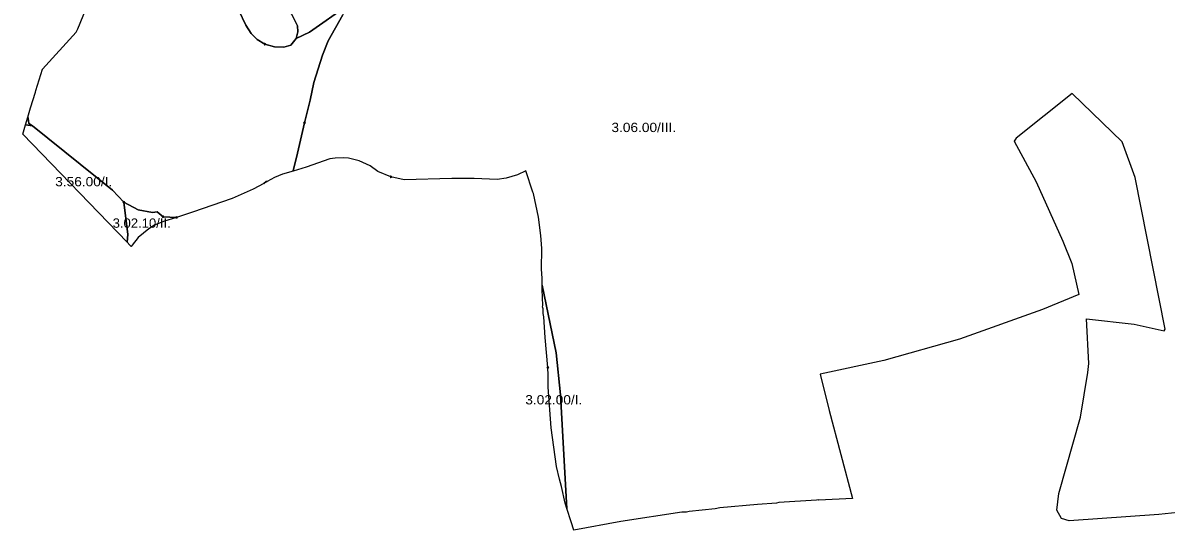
# Model space of a CAD drawing. Extents: x -650455 to -642254, y -1075222 to -1066610.
# Drawn here: x -645645 to -644416, y -1073659 to -1073114 of the extents above; entities that cross this region are included whole.
import ezdxf
from ezdxf.enums import TextEntityAlignment as Align

# ---------------------------------------------------------------- set-up
doc = ezdxf.new("R2010")
doc.units = 0
doc.header["$LTSCALE"] = 4
doc.header["$PDMODE"] = 32
doc.header["$PDSIZE"] = 2
for name, color, linetype, lineweight in [('1', 7, 'Continuous', 25), ('11', 7, 'Continuous', 13), ('12', 7, 'Continuous', 13), ('13', 7, 'Continuous', 13), ('14', 7, 'Continuous', 13)]:
    doc.layers.add(name, color=color, linetype=linetype, lineweight=lineweight)
doc.layers.add('2', color=7, linetype='Continuous')

msp = doc.modelspace()

# ---------------------------------------------------------------- linework, layer by layer
at = {"layer": '1'}
for points in [[(-645351.243, -1073131.207), (-645357.013, -1073138.376), (-645364.358, -1073140.474), (-645374.499, -1073140.125), (-645384.641, -1073137.152), (-645393.034, -1073132.256), (-645399.679, -1073125.611), (-645405.274, -1073116.694), (-645412.618, -1073101.131), (-645418.563, -1073077.351), (-645423.109, -1073054.795), (-645415.59, -1073061.089), (-645393.558, -1073075.428), (-645375.373, -1073085.744), (-645364.532, -1073094.137), (-645360.161, -1073098.159), (-645354.74, -1073107.426), (-645349.844, -1073117.568), (-645349.32, -1073124.038)], [(-645638.532, -1073222.307), (-645634.5, -1073225.001), (-645641.977, -1073223.681), (-645639.672, -1073215.65), (-645639.079, -1073216.724)], [(-645532, -1073341.501), (-645532.942, -1073349.981), (-645644.929, -1073233.97), (-645641.977, -1073223.681), (-645634.5, -1073225.001), (-645548.5, -1073294.001), (-645536.5, -1073307)], [(-645382.453, -1073284.826), (-645386.001, -1073286.755), (-645383.329, -1073284.731)], [(-645521, -1073315), (-645505.5, -1073318.001), (-645500.597, -1073317.109), (-645494.276, -1073322.5), (-645479.792, -1073323.208), (-645493.898, -1073327.697), (-645503.277, -1073331.676), (-645509.529, -1073335.37), (-645520.898, -1073344.89), (-645527.577, -1073353.132), (-645528.504, -1073354.578), (-645530.085, -1073352.941), (-645532.942, -1073349.981), (-645532, -1073341.501), (-645536.5, -1073307)], [(-645060.1, -1073635.952), (-645061.878, -1073630.295), (-645065.97, -1073612.516), (-645068.228, -1073604.614), (-645071.191, -1073590.784), (-645076.977, -1073549.296), (-645080.222, -1073505.551), (-645080.081, -1073492.851), (-645080.505, -1073484.384), (-645083.609, -1073452.21), (-645085.02, -1073430.198), (-645085.585, -1073426.529), (-645085.585, -1073421.449), (-645086.149, -1073419.472), (-645085.867, -1073417.78), (-645086.714, -1073400.563), (-645086.714, -1073396.177), (-645071.473, -1073468.855), (-645066.839, -1073513.793)]]:
    msp.add_lwpolyline(points, close=True, dxfattribs=at)
for points in [[(-645322.654, -1073149.042), (-645332.097, -1073178.418), (-645335.943, -1073197.478), (-645342.151, -1073221.608), (-645349.757, -1073254.306), (-645354.478, -1073273.19), (-645354.488, -1073273.432), (-645366.002, -1073276.823), (-645374.529, -1073280.517), (-645382.453, -1073284.826), (-645383.329, -1073284.731), (-645386.001, -1073286.755), (-645397.266, -1073292.881), (-645420.003, -1073302.828), (-645462.634, -1073317.748), (-645479.792, -1073323.208), (-645494.276, -1073322.5), (-645500.597, -1073317.109), (-645505.5, -1073318.001), (-645521, -1073315), (-645536.5, -1073307), (-645548.5, -1073294.001), (-645634.5, -1073225.001), (-645638.532, -1073222.307), (-645639.079, -1073216.724), (-645639.672, -1073215.65), (-645636.773, -1073205.545), (-645631.269, -1073188.612), (-645631.128, -1073186.919), (-645623.649, -1073164.198), (-645587.806, -1073124.405), (-645585.831, -1073120.596), (-645576.8, -1073098.864)], [(-645412.618, -1073101.131), (-645405.274, -1073116.694), (-645399.679, -1073125.611), (-645393.034, -1073132.256), (-645384.641, -1073137.152), (-645374.499, -1073140.125), (-645364.358, -1073140.474), (-645357.013, -1073138.376), (-645351.243, -1073131.207), (-645336.905, -1073124.213), (-645294.852, -1073094.837)], [(-645294.852, -1073094.837), (-645336.905, -1073124.213), (-645351.243, -1073131.207), (-645349.32, -1073124.038), (-645349.844, -1073117.568), (-645354.74, -1073107.426)], [(-645086.714, -1073396.177), (-645086.714, -1073388.427), (-645087.278, -1073378.832), (-645086.996, -1073356.537), (-645088.125, -1073342.708), (-645090.524, -1073322.952), (-645096.027, -1073297.551), (-645096.874, -1073295.999), (-645104.297, -1073273.411), (-645113.053, -1073277.391), (-645125.558, -1073281.086), (-645134.938, -1073282.648), (-645159.948, -1073281.511), (-645183.822, -1073281.511), (-645234.98, -1073282.791), (-645249.191, -1073279.665), (-645263.402, -1073273.98), (-645271.501, -1073267.869), (-645283.581, -1073262.328), (-645294.949, -1073259.77), (-645300.633, -1073259.2), (-645309.16, -1073259.627), (-645314.844, -1073260.48), (-645340.423, -1073269.29), (-645354.488, -1073273.432), (-645354.478, -1073273.19), (-645349.757, -1073254.306), (-645342.151, -1073221.608), (-645335.943, -1073197.478), (-645332.097, -1073178.418), (-645322.654, -1073149.042), (-645316.797, -1073133.48), (-645301.06, -1073105.503)], [(-645301.06, -1073105.503), (-645316.797, -1073133.48), (-645322.654, -1073149.042)], [(-644508.15, -1073538.007), (-644499.965, -1073489.748), (-644499.118, -1073480.04), (-644501.498, -1073432.196), (-644450.153, -1073438.099), (-644418.12, -1073445.155), (-644416.85, -1073443.462), (-644449.165, -1073280.335), (-644463.276, -1073242.235), (-644516.891, -1073190.139), (-644577.295, -1073238.143), (-644579.271, -1073241.528), (-644555.705, -1073285.133), (-644526.918, -1073348.634), (-644517.463, -1073372.622), (-644509.633, -1073406.043), (-644549.004, -1073422.171), (-644638.115, -1073454.186), (-644719.397, -1073476.905), (-644787.865, -1073491.654), (-644778.163, -1073530.809), (-644753.225, -1073625.103), (-644789.247, -1073627.05), (-644789.812, -1073626.485), (-644791.646, -1073627.05), (-644832.287, -1073629.59), (-644834.827, -1073630.155), (-644855.147, -1073631.566), (-644895.788, -1073635.376), (-644900.868, -1073636.223), (-644928.808, -1073639.185), (-644931.348, -1073639.89), (-644936.429, -1073640.033), (-645002.046, -1073649.911), (-645052.793, -1073659.198), (-645055.646, -1073650.122), (-645060.1, -1073635.952), (-645066.839, -1073513.793), (-645071.473, -1073468.855), (-645086.714, -1073396.177)], [(-644376.209, -1073637.35), (-644423.623, -1073642.431), (-644520.145, -1073649.204), (-644528.329, -1073646.806), (-644533.268, -1073637.633), (-644531.151, -1073619.854), (-644508.15, -1073538.007)]]:
    msp.add_lwpolyline(points, dxfattribs=at)
at = {"layer": '11'}
for points in [[(-645536.5, -1073307), (-645548.5, -1073294.001), (-645634.5, -1073225.001), (-645641.977, -1073223.681), (-645644.929, -1073233.97), (-645532.942, -1073349.981)], [(-645532.942, -1073349.981), (-645532, -1073341.501), (-645536.5, -1073307)]]:
    msp.add_lwpolyline(points, dxfattribs=at)
msp.add_lwpolyline([(-645080.505, -1073484.384), (-645080.081, -1073492.851), (-645080.222, -1073505.551), (-645076.977, -1073549.296), (-645071.191, -1073590.784), (-645068.228, -1073604.614), (-645065.97, -1073612.516), (-645061.878, -1073630.295), (-645060.1, -1073635.952), (-645066.839, -1073513.793), (-645071.473, -1073468.855), (-645086.714, -1073396.177), (-645086.714, -1073400.563), (-645085.867, -1073417.78), (-645086.149, -1073419.472), (-645085.585, -1073421.449), (-645085.585, -1073426.529), (-645085.02, -1073430.198), (-645083.609, -1073452.21)], close=True, dxfattribs=at)
for p in [(-645536.5, -1073307), (-645080.505, -1073484.384)]:
    msp.add_point(p, dxfattribs=at)
at = {"layer": '12'}
for points in [[(-645479.792, -1073323.208), (-645494.276, -1073322.5), (-645500.597, -1073317.109), (-645505.5, -1073318.001), (-645521, -1073315), (-645536.5, -1073307), (-645532, -1073341.501)], [(-645532, -1073341.501), (-645532.942, -1073349.981), (-645530.085, -1073352.941), (-645528.504, -1073354.578), (-645527.577, -1073353.132), (-645520.898, -1073344.89), (-645509.529, -1073335.37), (-645503.277, -1073331.676), (-645493.898, -1073327.697), (-645479.792, -1073323.208)]]:
    msp.add_lwpolyline(points, dxfattribs=at)
msp.add_point((-645479.792, -1073323.208), dxfattribs=at)
at = {"layer": '13'}
for points in [[(-645342.151, -1073221.608), (-645335.943, -1073197.478), (-645332.097, -1073178.418), (-645322.654, -1073149.042), (-645316.797, -1073133.48), (-645301.06, -1073105.503), (-645294.852, -1073094.837), (-645336.905, -1073124.213), (-645351.243, -1073131.207), (-645357.013, -1073138.376), (-645364.358, -1073140.474), (-645374.499, -1073140.125), (-645384.641, -1073137.152), (-645393.034, -1073132.256), (-645399.679, -1073125.611), (-645405.274, -1073116.694), (-645412.618, -1073101.131), (-645418.563, -1073077.351), (-645423.109, -1073054.795), (-645433.338, -1073026.118), (-645442.606, -1073007.758)], [(-645375.373, -1073085.744), (-645364.532, -1073094.137), (-645360.161, -1073098.159), (-645354.74, -1073107.426), (-645349.844, -1073117.568), (-645349.32, -1073124.038), (-645351.243, -1073131.207), (-645336.905, -1073124.213), (-645294.852, -1073094.837)], [(-645576.8, -1073098.864), (-645585.831, -1073120.596), (-645587.806, -1073124.405), (-645623.649, -1073164.198), (-645631.128, -1073186.919), (-645631.269, -1073188.612), (-645636.773, -1073205.545), (-645639.672, -1073215.65), (-645639.079, -1073216.724), (-645638.532, -1073222.307), (-645634.5, -1073225.001), (-645548.5, -1073294.001), (-645536.5, -1073307), (-645521, -1073315), (-645505.5, -1073318.001), (-645500.597, -1073317.109), (-645494.276, -1073322.5)], [(-645301.06, -1073105.503), (-645316.797, -1073133.48), (-645322.654, -1073149.042), (-645332.097, -1073178.418), (-645335.943, -1073197.478), (-645342.151, -1073221.608), (-645349.757, -1073254.306), (-645354.478, -1073273.19), (-645354.488, -1073273.432), (-645340.423, -1073269.29), (-645314.844, -1073260.48), (-645309.16, -1073259.627), (-645300.633, -1073259.2), (-645294.949, -1073259.77), (-645283.581, -1073262.328), (-645271.501, -1073267.869), (-645263.402, -1073273.98), (-645249.191, -1073279.665)], [(-644509.633, -1073406.043), (-644517.463, -1073372.622), (-644526.918, -1073348.634), (-644555.705, -1073285.133), (-644579.271, -1073241.528), (-644577.295, -1073238.143), (-644516.891, -1073190.139), (-644463.276, -1073242.235), (-644449.165, -1073280.335), (-644416.85, -1073443.462), (-644418.12, -1073445.155), (-644450.153, -1073438.099), (-644501.498, -1073432.196), (-644499.118, -1073480.04), (-644499.965, -1073489.748), (-644508.15, -1073538.007), (-644531.151, -1073619.854), (-644533.268, -1073637.633), (-644528.329, -1073646.806), (-644520.145, -1073649.204), (-644423.623, -1073642.431), (-644376.209, -1073637.35)], [(-645494.276, -1073322.5), (-645479.792, -1073323.208), (-645462.634, -1073317.748), (-645420.003, -1073302.828), (-645397.266, -1073292.881), (-645386.001, -1073286.755), (-645383.329, -1073284.731), (-645382.453, -1073284.826), (-645374.529, -1073280.517), (-645366.002, -1073276.823), (-645354.488, -1073273.432), (-645354.478, -1073273.19), (-645349.757, -1073254.306), (-645342.151, -1073221.608)], [(-645249.191, -1073279.665), (-645234.98, -1073282.791), (-645183.822, -1073281.511), (-645159.948, -1073281.511), (-645134.938, -1073282.648), (-645125.558, -1073281.086), (-645113.053, -1073277.391), (-645104.297, -1073273.411), (-645096.874, -1073295.999), (-645096.027, -1073297.551), (-645090.524, -1073322.952), (-645088.125, -1073342.708), (-645086.996, -1073356.537), (-645087.278, -1073378.832), (-645086.714, -1073388.427), (-645086.714, -1073396.177), (-645071.473, -1073468.855), (-645066.839, -1073513.793), (-645060.1, -1073635.952), (-645055.646, -1073650.122), (-645052.793, -1073659.198), (-645002.046, -1073649.911), (-644936.429, -1073640.033), (-644931.348, -1073639.89), (-644928.808, -1073639.185), (-644900.868, -1073636.223), (-644895.788, -1073635.376), (-644855.147, -1073631.566), (-644834.827, -1073630.155), (-644832.287, -1073629.59), (-644791.646, -1073627.05), (-644789.812, -1073626.485), (-644789.247, -1073627.05), (-644753.225, -1073625.103), (-644778.163, -1073530.809), (-644787.865, -1073491.654), (-644719.397, -1073476.905), (-644638.115, -1073454.186), (-644549.004, -1073422.171), (-644509.633, -1073406.043)]]:
    msp.add_lwpolyline(points, dxfattribs=at)
for p in [(-645342.151, -1073221.608), (-645249.191, -1073279.665), (-645494.276, -1073322.5)]:
    msp.add_point(p, dxfattribs=at)
at = {"layer": '14'}
for points in [[(-645364.532, -1073094.137), (-645375.373, -1073085.744), (-645393.558, -1073075.428), (-645415.59, -1073061.089), (-645423.109, -1073054.795), (-645418.563, -1073077.351), (-645412.618, -1073101.131), (-645405.274, -1073116.694), (-645399.679, -1073125.611), (-645393.034, -1073132.256), (-645384.641, -1073137.152)], [(-645384.641, -1073137.152), (-645374.499, -1073140.125), (-645364.358, -1073140.474), (-645357.013, -1073138.376), (-645351.243, -1073131.207), (-645349.32, -1073124.038), (-645349.844, -1073117.568), (-645354.74, -1073107.426), (-645360.161, -1073098.159), (-645364.532, -1073094.137)]]:
    msp.add_lwpolyline(points, dxfattribs=at)
msp.add_point((-645384.641, -1073137.152), dxfattribs=at)

# ---------------------------------------------------------------- texts
at = {"layer": '2'}
for s, width, p in [('3.06.00/III.', 1.1, (-644977.478, -1073231.6)), ('3.56.00/I.', 1.1, (-645579.497, -1073289.837)), ('3.02.10/II.', 1.05, (-645517.168, -1073334.373)), ('3.02.00/I.', 1.1, (-645074.164, -1073524.163))]:
    msp.add_text(s, height=10, dxfattribs=dict(at, width=width)).set_placement(p, align=Align.CENTER)

doc.saveas('drawing.dxf')
